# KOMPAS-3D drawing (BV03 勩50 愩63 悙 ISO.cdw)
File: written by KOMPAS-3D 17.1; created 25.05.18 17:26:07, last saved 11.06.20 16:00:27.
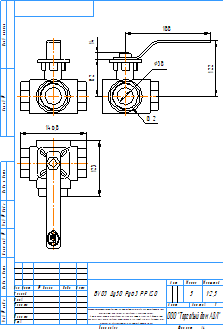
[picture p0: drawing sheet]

Sheet 1: A4, portrait

Title block, sheet 1: name: BV03 Ду50 Ру63 РР ISO; material: Сталь 20  ГОСТ 1050-88; mass: 5; sheets: 1; sheet format: A4; stored path: C:\Users\kka\KOMPAS_Work\!Trash\BV3 кран трехходовой шаровой\KOMPAS 2D\BV03 Ду50 Ру63 РР ISO.cdw

Views: Вид 1, Проекционный вид 2, Проекционный вид 3
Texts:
  kka
  adl
  Рама для чертежей
  Лит-Масса-Масштаб
  Материал-Предприятие
  Масштаб
  Изм.
  Лист
  № докум.
  Подп.
  Дата
  Лит.
  Разраб.
  Пров.
  Т.контр.
  Листов
  Внимание! Данный продукт является объектом авторского права ООО «Торговый Дом АДЛ».
  Запрещается изменение, копирование, распространение
  (в том числе путем копирования на другие сайты и ресурсы в Интернете)
  или любое иное использование информации и объектов без предварительного
  согласия правообладателя (ООО «Торговый Дом АДЛ»).
  Н.контр.
  Утв.
  ООО "Торговый дом АДЛ"
  Изменение
  Номер документа
  Подпись
  Обозначение документа
  Наименование изделия
  Масса изделия по ГОСТ 2.109-73
  Порядковый номер листа
  Общее количество листов в документе
  Характер работы, выполненной лицом, подписавшим документ
  Наименование или индекс предприятия, выпускающего документ
  Инв. № подл.
  Подп. и дата
  Взам. инв. №
  Инв. № дубл.
  Инвентарный номер подлинника по ГОСТ 2.501-68
  Подпись принявшего подлинник в отдел технической документации
  Инвентарный номер подлинника, взамен которого выпущен данный подлинник
  Инвентарный номер дубликата по ГОСТ 2.502-68
  Подпись принявшего дубликат в отдел технической документации
  Справ. №
  Перв. примен.
  Обозначение документа, взамен или на основании которого выпущен данный документ
  Обозначение документа, в котором впервые записан данный документ
  Подпись лица, копировавшего чертеж
  Обозначение формата листа
  !Рама для чертежа
Dimensions and other numbers on the sheet: 188; 122; 82; 14; 38; 146,8; 123; 1:2,5; 1; 5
